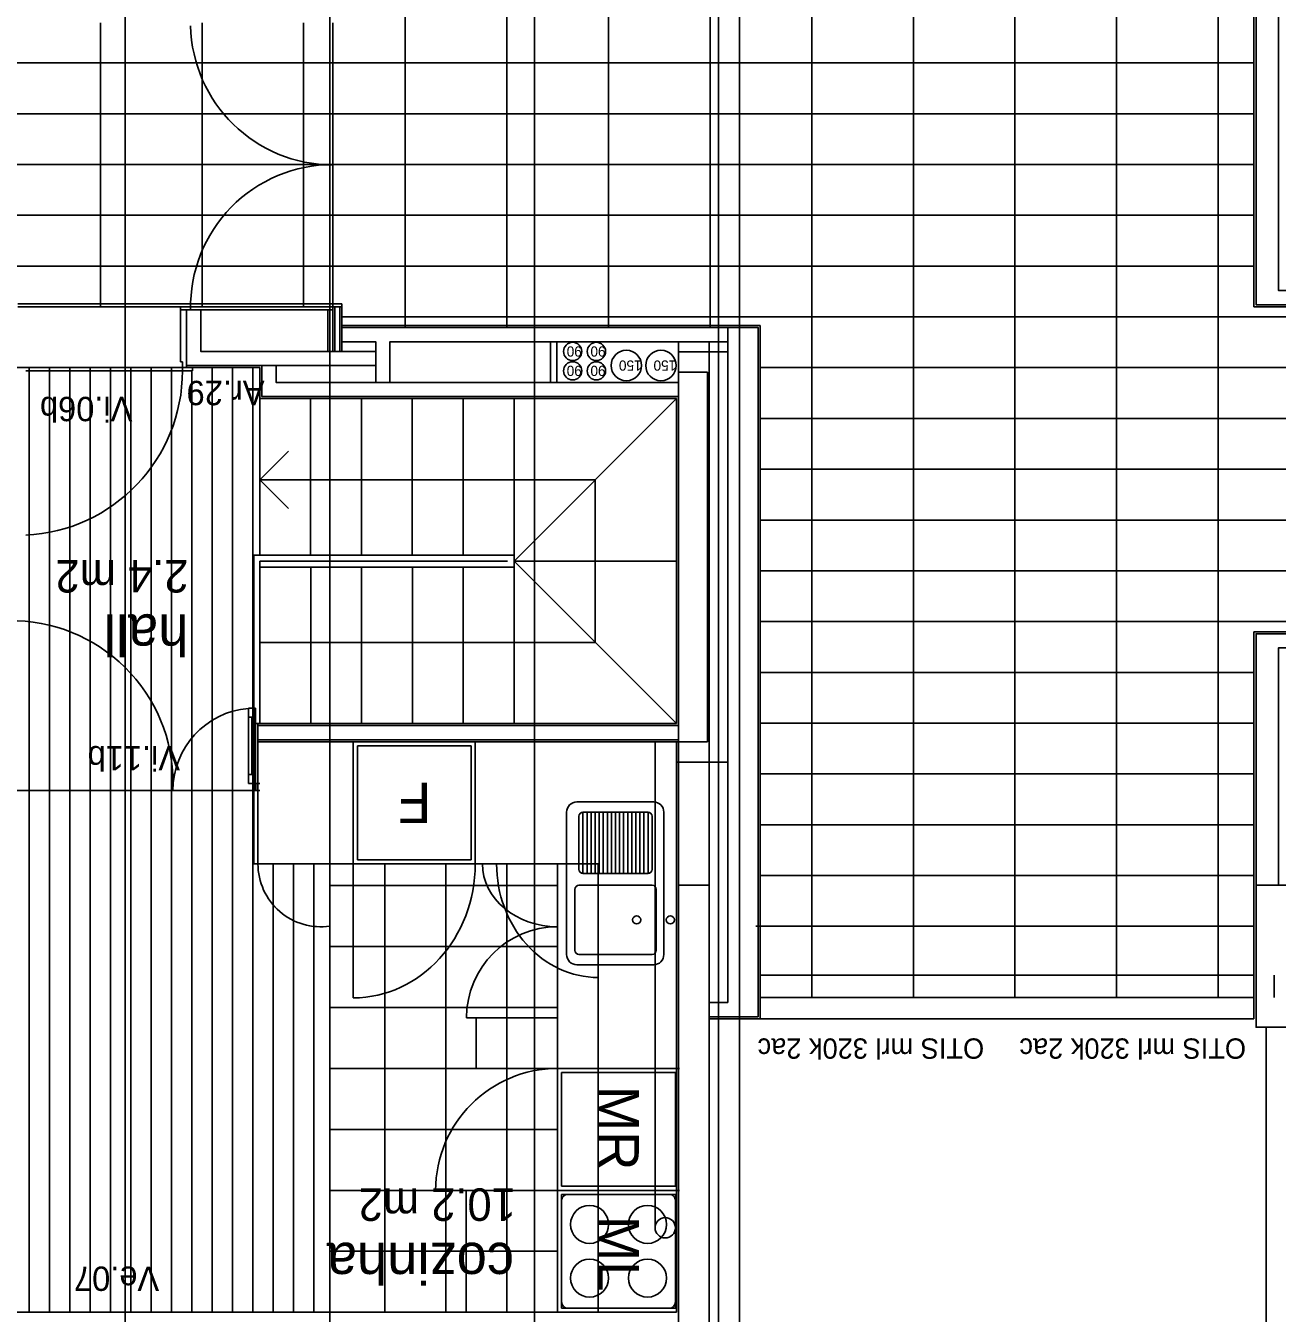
# Model space of a CAD drawing. Extents: x 1248 to 1356, y -443 to -224.
# Drawn here: x 1312.15 to 1318.31, y -243.58 to -237.24 of the extents above; entities that cross this region are included whole.
import ezdxf

# ---------------------------------------------------------------- set-up
doc = ezdxf.new("R2010")
doc.units = 0
for name, color, linetype in [('corte', 7, 'Continuous'), ('estereoctomias', 7, 'Continuous'), ('Level 1', 7, 'Continuous'), ('Level 10', 7, 'Continuous'), ('Level 11', 7, 'Continuous'), ('Level 13', 7, 'Continuous'), ('Level 2', 7, 'Continuous'), ('Level 3', 7, 'Continuous'), ('Level 36', 7, 'Continuous'), ('Level 4', 7, 'Continuous'), ('Level 40', 7, 'Continuous'), ('Level 41', 7, 'Continuous'), ('Level 60', 7, 'Continuous'), ('mob-fixo', 7, 'Continuous'), ('projeccao', 7, 'Continuous'), ('revestimentos', 7, 'Continuous'), ('vermelhos-cont', 7, 'Continuous'), ('vermelhos-tracej', 7, 'Continuous')]:
    doc.layers.add(name, color=color, linetype=linetype)

msp = doc.modelspace()

# ---------------------------------------------------------------- linework, layer by layer
at = {"layer": 'corte'}
for p, q in [((1318.2044, -236.5639), (1318.2044, -238.614)), ((1319.736, -238.614), (1318.2044, -238.614)), ((1312.9419, -238.914), (1312.9419, -238.639)), ((1313.0119, -238.844), (1313.0119, -238.639)), ((1315.6049, -238.7263), (1315.6049, -242.049)), ((1315.7544, -238.7263), (1315.7544, -242.119)), ((1313.7069, -238.7963), (1313.8727, -238.7963)), ((1314.7334, -238.7963), (1314.7334, -238.9963)), ((1314.7634, -238.7963), (1314.7634, -238.9963)), ((1315.3634, -242.7713), (1315.3634, -238.7963)), ((1315.5134, -238.7963), (1315.5134, -243.7713)), ((1313.0119, -238.844), (1313.8727, -238.844)), ((1312.9419, -238.914), (1313.3127, -238.914)), ((1313.3127, -239.0663), (1313.3127, -238.914)), ((1313.3827, -238.9963), (1313.3827, -238.914)), ((1313.3827, -238.914), (1313.8727, -238.914)), ((1313.9427, -238.9963), (1315.3634, -238.9963)), ((1313.9427, -238.9963), (1315.3634, -238.9963)), ((1313.9427, -238.9963), (1315.3634, -238.9963)), ((1315.3634, -242.7713), (1315.3634, -239.0763)), ((1318.2044, -241.4713), (1318.2044, -240.234)), ((1315.6049, -242.049), (1315.5134, -242.049)), ((1315.7544, -242.119), (1315.5134, -242.119))]:
    msp.add_line(p, q, dxfattribs=at)
for points in [[(1315.5134, -243.7713), (1315.3634, -243.7713), (1315.3634, -241.4713), (1315.5134, -241.4713)], [(1318.4044, -242.1713), (1318.2044, -242.1713), (1318.2044, -241.4713), (1318.4044, -241.4713)], [(1318.4044, -243.7713), (1318.2544, -243.7713), (1318.2544, -242.1713), (1318.4044, -242.1713)]]:
    msp.add_lwpolyline(points, close=True, dxfattribs=at)
at = {"layer": 'estereoctomias'}
msp.add_line((1312.1119, -238.624), (1312.9119, -238.624), dxfattribs=at)
for points in [[(1319.701, -237.584), (1319.701, -238.424), (1319.736, -238.424), (1319.736, -238.614), (1318.2044, -238.614), (1318.2044, -236.5639), (1318.3144, -236.5639), (1318.3144, -238.544), (1319.631, -238.544), (1319.631, -238.244), (1319.201, -238.244), (1319.201, -238.544), (1319.171, -238.544), (1319.171, -238.244), (1318.5103, -238.244), (1318.5103, -238.5239), (1318.5103, -238.544), (1318.4003, -238.544), (1318.4003, -236.7713), (1318.5103, -236.7713), (1318.5103, -238.094), (1319.551, -238.094), (1319.551, -237.584)], [(1313.8727, -238.844), (1313.8727, -238.914), (1312.9419, -238.914), (1312.9419, -238.639), (1313.0119, -238.639), (1313.0119, -238.844)], [(1315.6049, -238.7963), (1313.9427, -238.7963), (1313.9427, -238.9963), (1313.8727, -238.9963), (1313.8727, -238.7963), (1313.7069, -238.7963), (1313.7069, -238.7263), (1315.6049, -238.7263)], [(1315.6049, -242.049), (1315.5134, -242.049), (1315.5134, -242.119), (1315.7544, -242.119), (1315.7544, -238.7263), (1315.6049, -238.7263)], [(1315.5134, -238.7963), (1315.5134, -241.4713), (1315.3634, -241.4713), (1315.3634, -240.7563), (1313.2934, -240.7563), (1313.2934, -240.6863), (1315.3634, -240.6863), (1315.3634, -238.7963)], [(1315.3634, -239.0663), (1313.3127, -239.0663), (1313.3127, -238.914), (1313.3827, -238.914), (1313.3827, -238.9963), (1314.7334, -238.9963), (1314.7334, -238.7963), (1314.7634, -238.7963), (1314.7634, -238.9963), (1315.3634, -238.9963)], [(1319.736, -240.234), (1319.736, -240.304), (1319.701, -240.304), (1319.701, -241.264), (1319.551, -241.264), (1319.551, -240.754), (1318.5144, -240.754), (1318.5144, -242.014), (1318.4003, -242.014), (1318.4003, -240.304), (1318.5144, -240.304), (1318.5144, -240.604), (1319.171, -240.604), (1319.171, -240.304), (1319.201, -240.304), (1319.201, -240.604), (1319.631, -240.604), (1319.631, -240.304), (1318.3144, -240.304), (1318.3144, -241.4713), (1318.2044, -241.4713), (1318.2044, -240.234)]]:
    msp.add_lwpolyline(points, close=True, dxfattribs=at)
at = {"layer": 'Level 1'}
for p, q in [((1313.0119, -238.639), (1312.9419, -238.639)), ((1313.7069, -238.7263), (1313.7069, -238.7963)), ((1315.7544, -238.7263), (1313.7069, -238.7263)), ((1313.8727, -238.7963), (1313.8727, -238.844)), ((1315.6049, -238.7963), (1313.9427, -238.7963)), ((1313.9427, -238.7963), (1313.9427, -238.9963)), ((1313.8727, -238.914), (1313.8727, -238.9963)), ((1313.8727, -238.9963), (1313.3827, -238.9963)), ((1315.3634, -239.0663), (1313.3127, -239.0663)), ((1318.2044, -240.234), (1319.736, -240.234)), ((1313.2934, -240.6863), (1313.2934, -240.7563)), ((1315.3634, -240.6863), (1313.2934, -240.6863)), ((1315.3634, -240.7563), (1313.2934, -240.7563))]:
    msp.add_line(p, q, dxfattribs=at)
at = {"layer": 'Level 10'}
for p, q in [((1316.0183, -235.374), (1316.0183, -242.024)), ((1316.5183, -235.374), (1316.5183, -242.024)), ((1317.0183, -236.624), (1317.0183, -242.024)), ((1317.5183, -236.624), (1317.5183, -242.024)), ((1318.0183, -236.624), (1318.0183, -242.024)), ((1314.0183, -237.124), (1314.0183, -238.724)), ((1314.5183, -237.124), (1314.5183, -238.724)), ((1315.0183, -237.124), (1315.0183, -238.724)), ((1315.5183, -237.124), (1315.5183, -238.724)), ((1312.5183, -237.2259), (1312.5183, -238.624)), ((1313.0183, -237.2259), (1313.0183, -238.624)), ((1313.5183, -237.2259), (1313.5183, -238.624)), ((1296.6633, -237.424), (1318.1944, -237.424)), ((1299.1415, -237.674), (1318.1944, -237.674)), ((1299.1415, -237.924), (1318.1944, -237.924)), ((1299.1415, -238.174), (1318.1944, -238.174)), ((1309.5183, -238.424), (1318.1944, -238.424)), ((1313.7069, -238.674), (1319.671, -238.674)), ((1315.7433, -238.674), (1318.2933, -238.674)), ((1312.9219, -238.924), (1312.0919, -238.924)), ((1312.1677, -243.574), (1312.1677, -238.924)), ((1312.2677, -243.574), (1312.2677, -238.924)), ((1312.3677, -243.574), (1312.3677, -238.924)), ((1312.4677, -243.574), (1312.4677, -238.924)), ((1312.5677, -243.574), (1312.5677, -238.924)), ((1312.6677, -243.574), (1312.6677, -238.924)), ((1312.7677, -243.574), (1312.7677, -238.924)), ((1312.8677, -243.574), (1312.8677, -238.924)), ((1312.9677, -243.574), (1312.9677, -238.939)), ((1313.0677, -243.574), (1313.0677, -238.924)), ((1313.1677, -243.574), (1313.1677, -238.924)), ((1313.2677, -240.7313), (1313.2677, -238.924)), ((1348.9433, -238.924), (1315.7644, -238.924)), ((1347.9933, -239.174), (1315.7633, -239.174)), ((1318.2933, -239.174), (1315.7644, -239.174)), ((1347.9933, -239.424), (1315.7633, -239.424)), ((1318.2933, -239.424), (1315.7644, -239.424)), ((1347.9933, -239.674), (1315.7633, -239.674)), ((1318.2933, -239.674), (1315.7644, -239.674)), ((1347.9933, -239.924), (1315.7633, -239.924)), ((1318.2933, -239.924), (1315.7644, -239.924)), ((1319.671, -240.174), (1315.7633, -240.174)), ((1318.2933, -240.174), (1315.7644, -240.174)), ((1318.1944, -240.424), (1315.7644, -240.424)), ((1318.1944, -240.674), (1315.7644, -240.674)), ((1313.2677, -243.574), (1313.2677, -240.7663)), ((1318.1944, -240.924), (1315.7644, -240.924)), ((1318.1944, -241.174), (1315.7644, -241.174)), ((1313.3677, -243.574), (1313.3677, -241.3663)), ((1313.4677, -243.574), (1313.4677, -241.3663)), ((1313.5677, -243.574), (1313.5677, -241.3663)), ((1313.6473, -243.574), (1313.6473, -241.3663)), ((1313.9177, -243.574), (1313.9177, -241.3663)), ((1314.2177, -243.574), (1314.2177, -241.3663)), ((1314.5177, -243.574), (1314.5177, -241.3663)), ((1314.7677, -241.474), (1313.6473, -241.474)), ((1318.1944, -241.424), (1315.7644, -241.424)), ((1318.1944, -241.674), (1315.7433, -241.674)), ((1314.7677, -241.774), (1313.6473, -241.774)), ((1318.1944, -241.914), (1315.7644, -241.914)), ((1318.2933, -241.914), (1318.2933, -242.024)), ((1318.1944, -242.024), (1315.7644, -242.024)), ((1314.7677, -242.074), (1313.6473, -242.074)), ((1314.7677, -242.374), (1313.6473, -242.374)), ((1314.7677, -242.674), (1313.6473, -242.674)), ((1314.7677, -242.974), (1313.6473, -242.974)), ((1314.7677, -243.274), (1313.6473, -243.274))]:
    msp.add_line(p, q, dxfattribs=at)
at = {"layer": 'Level 11'}
for p, q in [((1313.7827, -241.3463), (1313.7827, -240.7863)), ((1313.7827, -240.7863), (1314.3427, -240.7863)), ((1314.3427, -241.3463), (1314.3427, -240.7863)), ((1314.8728, -241.3939), (1314.8728, -241.1324)), ((1315.2128, -241.1124), (1314.8928, -241.1124)), ((1314.8928, -241.4139), (1314.8928, -241.1124)), ((1314.9128, -241.4139), (1314.9128, -241.1124)), ((1314.9328, -241.4139), (1314.9328, -241.1124)), ((1314.9528, -241.4139), (1314.9528, -241.1124)), ((1314.9728, -241.4139), (1314.9728, -241.1124)), ((1314.9928, -241.4139), (1314.9928, -241.1124)), ((1315.0128, -241.4139), (1315.0128, -241.1124)), ((1315.0328, -241.4139), (1315.0328, -241.1124)), ((1315.0528, -241.4139), (1315.0528, -241.1124)), ((1315.0728, -241.4139), (1315.0728, -241.1124)), ((1315.0928, -241.4139), (1315.0928, -241.1124)), ((1315.1128, -241.4139), (1315.1128, -241.1124)), ((1315.1328, -241.4139), (1315.1328, -241.1124)), ((1315.1528, -241.4139), (1315.1528, -241.1124)), ((1315.1728, -241.4139), (1315.1728, -241.1124)), ((1315.1928, -241.4139), (1315.1928, -241.1124)), ((1315.2128, -241.4139), (1315.2128, -241.1124)), ((1315.2328, -241.3939), (1315.2328, -241.1324)), ((1314.3427, -241.3463), (1313.7827, -241.3463)), ((1315.2128, -241.4139), (1314.8928, -241.4139)), ((1314.8728, -241.4724), (1315.2328, -241.4724)), ((1314.8528, -241.7924), (1314.8528, -241.4924)), ((1315.2528, -241.4924), (1315.2528, -241.7924)), ((1315.2328, -241.8124), (1314.8728, -241.8124)), ((1314.8177, -242.9939), (1315.3177, -242.9939)), ((1314.7877, -243.0239), (1314.7877, -243.5239)), ((1315.3477, -243.0239), (1315.3477, -243.5239)), ((1314.8177, -243.5539), (1315.3177, -243.5539))]:
    msp.add_line(p, q, dxfattribs=at)
for points in [[(1315.2406, -241.0621), (1314.8622, -241.0621)], [(1314.8122, -241.1121), (1314.8122, -241.8136)], [(1315.2906, -241.8136), (1315.2906, -241.1121)], [(1314.8622, -241.8636), (1315.2406, -241.8636)]]:
    msp.add_lwpolyline(points, dxfattribs=at)
for centre, radius in [((1315.1568, -241.6424), 0.0199), ((1315.3227, -241.6424), 0.0199), ((1314.9251, -243.1417), 0.0936), ((1315.2103, -243.1417), 0.0936), ((1314.9251, -243.406), 0.0936), ((1315.2103, -243.406), 0.0936)]:
    msp.add_circle(centre, radius, dxfattribs=at)
for centre, radius, start, end in [((1314.8622, -241.1121), 0.05, 90, 180), ((1315.2406, -241.1121), 0.05, 0, 90), ((1314.8928, -241.1324), 0.02, 90, 180), ((1315.2128, -241.1324), 0.02, 360, 90), ((1314.8928, -241.3939), 0.02, 180, 270), ((1315.2128, -241.3939), 0.02, 270, 360), ((1314.8728, -241.4924), 0.02, 90, 180), ((1315.2328, -241.4924), 0.02, 360, 90), ((1314.8728, -241.7924), 0.02, 180, 270), ((1315.2328, -241.7924), 0.02, 270, 0), ((1314.8622, -241.8135), 0.05, 180, 270), ((1315.2406, -241.8135), 0.05, 270, 0), ((1314.8177, -243.0239), 0.03, 89.9999, 179.99991), ((1315.3177, -243.0239), 0.03, 359.9998, 90.00015), ((1314.8177, -243.5239), 0.03, 179.99998, 269.99995), ((1315.3177, -243.5239), 0.03, 270.00001, 359.99979)]:
    msp.add_arc(centre, radius, start, end, dxfattribs=at)
at = {"layer": 'Level 13'}
for p, q in [((1312.9119, -238.639), (1312.9119, -238.624)), ((1312.9619, -238.624), (1312.9119, -238.624)), ((1313.6619, -238.624), (1312.9519, -238.624)), ((1313.6619, -238.624), (1312.9519, -238.624)), ((1313.6619, -238.624), (1312.9619, -238.624)), ((1312.9619, -238.639), (1312.9619, -238.624)), ((1313.6619, -238.624), (1313.6619, -238.609)), ((1313.6619, -238.609), (1313.7069, -238.609)), ((1313.6619, -238.639), (1313.6619, -238.624)), ((1313.6619, -238.624), (1313.7069, -238.624)), ((1313.6619, -238.844), (1313.6619, -238.624)), ((1313.6719, -238.624), (1313.6719, -238.844)), ((1313.6969, -238.624), (1313.6969, -238.844)), ((1313.7069, -238.624), (1313.7069, -238.609)), ((1313.7069, -238.644), (1313.7069, -238.624)), ((1312.9119, -238.639), (1312.9119, -238.895)), ((1313.6619, -238.639), (1312.9119, -238.639)), ((1312.9419, -238.924), (1312.9419, -238.639)), ((1313.7069, -238.644), (1313.7069, -238.844)), ((1312.9119, -238.895), (1312.9219, -238.895)), ((1312.9219, -238.895), (1312.9219, -238.924)), ((1313.2464, -240.9713), (1313.2464, -240.5997)), ((1313.2814, -240.5997), (1313.2464, -240.5997)), ((1313.2814, -240.6447), (1313.2464, -240.6447)), ((1313.2814, -240.9713), (1313.2814, -240.5997)), ((1313.2734, -240.6763), (1313.2734, -241.3663)), ((1313.2934, -240.6763), (1313.2734, -240.6763)), ((1313.2934, -240.6763), (1313.2934, -241.3663)), ((1313.2464, -240.9263), (1313.2814, -240.9263)), ((1313.2464, -240.9713), (1313.2814, -240.9713)), ((1313.2834, -240.9713), (1313.2834, -241.0063)), ((1313.2834, -240.9713), (1313.3034, -240.9713)), ((1313.2834, -241.0063), (1313.3034, -241.0063)), ((1313.2734, -241.3663), (1313.2934, -241.3663))]:
    msp.add_line(p, q, dxfattribs=at)
msp.add_lwpolyline([(1312.9719, -238.939), (1312.9219, -238.939), (1312.9219, -238.924), (1312.9719, -238.924)], close=True, dxfattribs=at)
at = {"layer": 'Level 2'}
for p, q in [((1313.3027, -239.0763), (1313.3027, -239.8463)), ((1313.5527, -239.0763), (1313.5527, -239.8463)), ((1313.8027, -239.0763), (1313.8027, -239.8463)), ((1314.0527, -239.0763), (1314.0527, -239.8463)), ((1314.3027, -239.0763), (1314.3027, -239.8463)), ((1314.5534, -239.0763), (1314.5534, -239.8463)), ((1314.5534, -239.8763), (1315.3534, -239.0763)), ((1313.4441, -239.3349), (1313.3027, -239.4763)), ((1314.9534, -239.4763), (1313.3027, -239.4763)), ((1313.4441, -239.6177), (1313.3027, -239.4763)), ((1314.9534, -239.4763), (1314.9534, -240.2763)), ((1314.5534, -239.8463), (1313.2734, -239.8463)), ((1313.2734, -240.6763), (1313.2734, -239.8463)), ((1314.521, -239.8763), (1313.3034, -239.8763)), ((1313.3034, -240.6763), (1313.3034, -239.8763)), ((1314.5534, -239.9063), (1314.5534, -239.8463)), ((1315.3534, -239.8763), (1314.5534, -239.8763)), ((1314.5534, -239.8763), (1315.3534, -240.6763)), ((1314.5534, -239.9063), (1313.3034, -239.9063)), ((1313.5534, -239.9063), (1313.5534, -240.6763)), ((1313.8034, -239.9063), (1313.8034, -240.6763)), ((1314.0534, -239.9063), (1314.0534, -240.6763)), ((1314.3034, -239.9063), (1314.3034, -240.6763)), ((1314.5534, -239.9063), (1314.5534, -240.6763)), ((1313.3034, -240.2763), (1314.9534, -240.2763)), ((1313.7627, -241.3663), (1313.7627, -240.7663)), ((1314.3627, -241.3663), (1314.3627, -240.7663)), ((1314.7677, -241.3663), (1313.2934, -241.3663)), ((1314.7677, -241.3663), (1313.5177, -241.3663)), ((1314.7677, -241.3663), (1313.5177, -241.3663)), ((1314.7677, -243.574), (1314.7677, -241.3663)), ((1318.1944, -242.129), (1315.7644, -242.129)), ((1313.6473, -243.574), (1311.6319, -243.574))]:
    msp.add_line(p, q, dxfattribs=at)
at = {"layer": 'Level 3'}
for p, q in [((1314.9677, -241.3663), (1314.7677, -241.3663)), ((1314.9677, -243.574), (1314.9677, -241.3663))]:
    msp.add_line(p, q, dxfattribs=at)
at = {"layer": 'Level 36'}
for p, q in [((1313.2629, -240.9263), (1313.2629, -240.6447)), ((1313.2649, -240.9263), (1313.2649, -240.6447))]:
    msp.add_line(p, q, dxfattribs=at)
at = {"layer": 'Level 4'}
for p, q in [((1313.6619, -237.2259), (1313.6619, -237.9259)), ((1313.6619, -238.624), (1313.6619, -237.924)), ((1312.1119, -238.609), (1313.6619, -238.609)), ((1313.6369, -238.844), (1313.6369, -238.639)), ((1312.9219, -238.939), (1312.1509, -238.939)), ((1313.6473, -241.6763), (1313.6473, -240.7663)), ((1313.2814, -240.9713), (1313.2814, -241.0063)), ((1312.0719, -241.0063), (1313.2957, -241.0063)), ((1313.7627, -242.0263), (1313.7627, -241.3663)), ((1314.7677, -242.1243), (1314.3197, -242.1243)), ((1314.3677, -242.374), (1314.3677, -242.1243)), ((1314.7677, -242.374), (1314.3677, -242.374)), ((1314.7677, -242.374), (1315.3677, -242.374)), ((1314.7877, -242.394), (1315.3477, -242.394)), ((1314.7877, -242.394), (1314.7877, -242.954)), ((1315.3477, -242.394), (1315.3477, -242.954)), ((1314.7677, -242.974), (1314.1677, -242.974)), ((1314.3177, -242.974), (1314.3177, -243.574)), ((1315.3677, -242.974), (1314.7677, -242.974)), ((1314.7877, -242.954), (1315.3477, -242.954)), ((1315.3477, -242.994), (1314.7877, -242.994)), ((1314.7877, -243.554), (1314.7877, -242.994)), ((1315.3477, -242.994), (1315.3477, -243.554)), ((1315.3477, -243.554), (1314.7877, -243.554))]:
    msp.add_line(p, q, dxfattribs=at)
for centre, radius, start, end in [((1313.6619, -237.2259), 0.7, 181.22786, 270), ((1313.6619, -238.624), 0.7, 90, 181.22786), ((1314.7677, -242.1243), 0.448, 90, 180), ((1314.7677, -242.974), 0.6, 90, 180)]:
    msp.add_arc(centre, radius, start, end, dxfattribs=at)
for centre, major_axis, ratio, start_param, end_param in [((1312.1159, -238.939), (0, -0.81), 0.995105, 0.043492, 1.570796), ((1313.602, -241.3663), (0, -0.3103), 0.994255, 4.712414, 6.430695), ((1313.7627, -241.3663), (0, -0.66), 0.909091, 0, 1.570796), ((1314.7677, -241.3663), (-0.37, 0), 0.837838, 0, 1.570796), ((1314.9677, -241.3663), (0, 0.56), 0.892857, 1.570796, 3.141593)]:
    msp.add_ellipse(centre, major_axis=major_axis, ratio=ratio, start_param=start_param, end_param=end_param, dxfattribs=at)
at = {"layer": 'Level 41'}
for centre, radius in [((1314.842, -238.8443), 0.045), ((1314.9588, -238.8443), 0.045), ((1315.1061, -238.9135), 0.075), ((1315.2764, -238.9135), 0.075), ((1314.842, -238.9397), 0.045), ((1314.9588, -238.9397), 0.045)]:
    msp.add_circle(centre, radius, dxfattribs=at)
at = {"layer": 'mob-fixo'}
for p, q in [((1315.6049, -240.8663), (1315.6049, -238.7963)), ((1315.3634, -238.8463), (1315.6049, -238.8463)), ((1315.3634, -238.9463), (1315.5049, -238.9463)), ((1315.5049, -240.7663), (1315.5049, -238.9463)), ((1315.2477, -243.1583), (1315.2477, -240.7663)), ((1315.2477, -240.7663), (1315.5049, -240.7663)), ((1315.3534, -240.8663), (1315.6049, -240.8663))]:
    msp.add_line(p, q, dxfattribs=at)
msp.add_circle((1315.2977, -243.1583), 0.05, dxfattribs=at)
at = {"layer": 'projeccao'}
for centre, radius, start, end in [((1312.0796, -240.9656), 0.7962, 357.07034, 87.89077), ((1313.2814, -241.0063), 0.4066, 94.93785, 180)]:
    msp.add_arc(centre, radius, start, end, dxfattribs=at)
at = {"layer": 'revestimentos'}
for p, q in [((1318.1944, -234.364), (1318.1944, -238.624)), ((1319.726, -238.624), (1318.1944, -238.624)), ((1315.7644, -238.7163), (1313.7069, -238.7163)), ((1315.7644, -238.7163), (1315.7644, -242.129)), ((1312.9719, -238.924), (1313.3027, -238.924)), ((1313.3027, -239.0763), (1313.3027, -238.924)), ((1313.3027, -239.0763), (1315.3534, -239.0763)), ((1315.3534, -240.6763), (1315.3534, -239.0763)), ((1318.1944, -242.129), (1318.1944, -240.224)), ((1318.1944, -240.224), (1319.736, -240.224)), ((1315.3534, -240.6763), (1313.2934, -240.6763)), ((1315.3534, -240.7663), (1313.2934, -240.7663)), ((1315.3534, -243.574), (1315.3534, -240.7663)), ((1315.6049, -242.049), (1315.5134, -242.049)), ((1315.7644, -242.129), (1315.5134, -242.129)), ((1313.6473, -243.574), (1313.6473, -243.924)), ((1315.3534, -243.574), (1313.6473, -243.574))]:
    msp.add_line(p, q, dxfattribs=at)
at = {"layer": 'vermelhos-cont'}
msp.add_line((1315.5589, -250.7923), (1315.5589, -229.6198), dxfattribs=at)
at = {"layer": 'vermelhos-tracej'}
for p, q in [((1312.6398, -246.757), (1312.6398, -236.1407)), ((1313.6473, -246.757), (1313.6473, -236.1407)), ((1314.6548, -246.757), (1314.6548, -236.1407)), ((1315.6623, -246.757), (1315.6623, -236.1407))]:
    msp.add_line(p, q, dxfattribs=at)

# ---------------------------------------------------------------- texts
at = {"layer": 'Level 1'}
for p in [(1316.8668, -242.2259), (1318.1551, -242.2259)]:
    msp.add_text('OTIS mrl 320k 2ac', height=0.1, rotation=180, dxfattribs=at).set_placement(p)
at = {"layer": 'Level 11'}
for s, rotation, p in [('F', 180, (1314.1466, -240.9663)), ('MR', 270, (1314.9677, -242.4603)), ('ML', 270, (1314.9677, -243.1))]:
    msp.add_text(s, height=0.2, rotation=rotation, dxfattribs=at).set_placement(p)
at = {"layer": 'Level 40'}
for s, p in [('Ar.29', (1313.3259, -238.9888)), ('Vi.06b', (1312.6758, -239.0676)), ('Vi.11b', (1312.9103, -240.7869)), ('Ve.07', (1312.8075, -243.3489))]:
    msp.add_text(s, height=0.12, rotation=180.00001, dxfattribs=at).set_placement(p)
at = {"layer": 'Level 41'}
for s, p in [('90', (1314.887, -238.8193)), ('90', (1315.0038, -238.8193)), ('90', (1314.887, -238.9147)), ('90', (1315.0038, -238.9147)), ('150', (1315.1811, -238.8885)), ('150', (1315.3514, -238.8885))]:
    msp.add_text(s, height=0.05, rotation=180, dxfattribs=at).set_placement(p)
at = {"layer": 'Level 60'}
for s, height, p in [('2.4 m2', 0.16, (1312.9513, -239.8708)), ('hall', 0.2, (1312.9513, -240.1386)), ('10.2 m2', 0.16, (1314.5623, -242.9642)), ('cozinha', 0.2, (1314.5537, -243.232))]:
    msp.add_text(s, height=height, rotation=180, dxfattribs=at).set_placement(p)

doc.saveas('drawing.dxf')
